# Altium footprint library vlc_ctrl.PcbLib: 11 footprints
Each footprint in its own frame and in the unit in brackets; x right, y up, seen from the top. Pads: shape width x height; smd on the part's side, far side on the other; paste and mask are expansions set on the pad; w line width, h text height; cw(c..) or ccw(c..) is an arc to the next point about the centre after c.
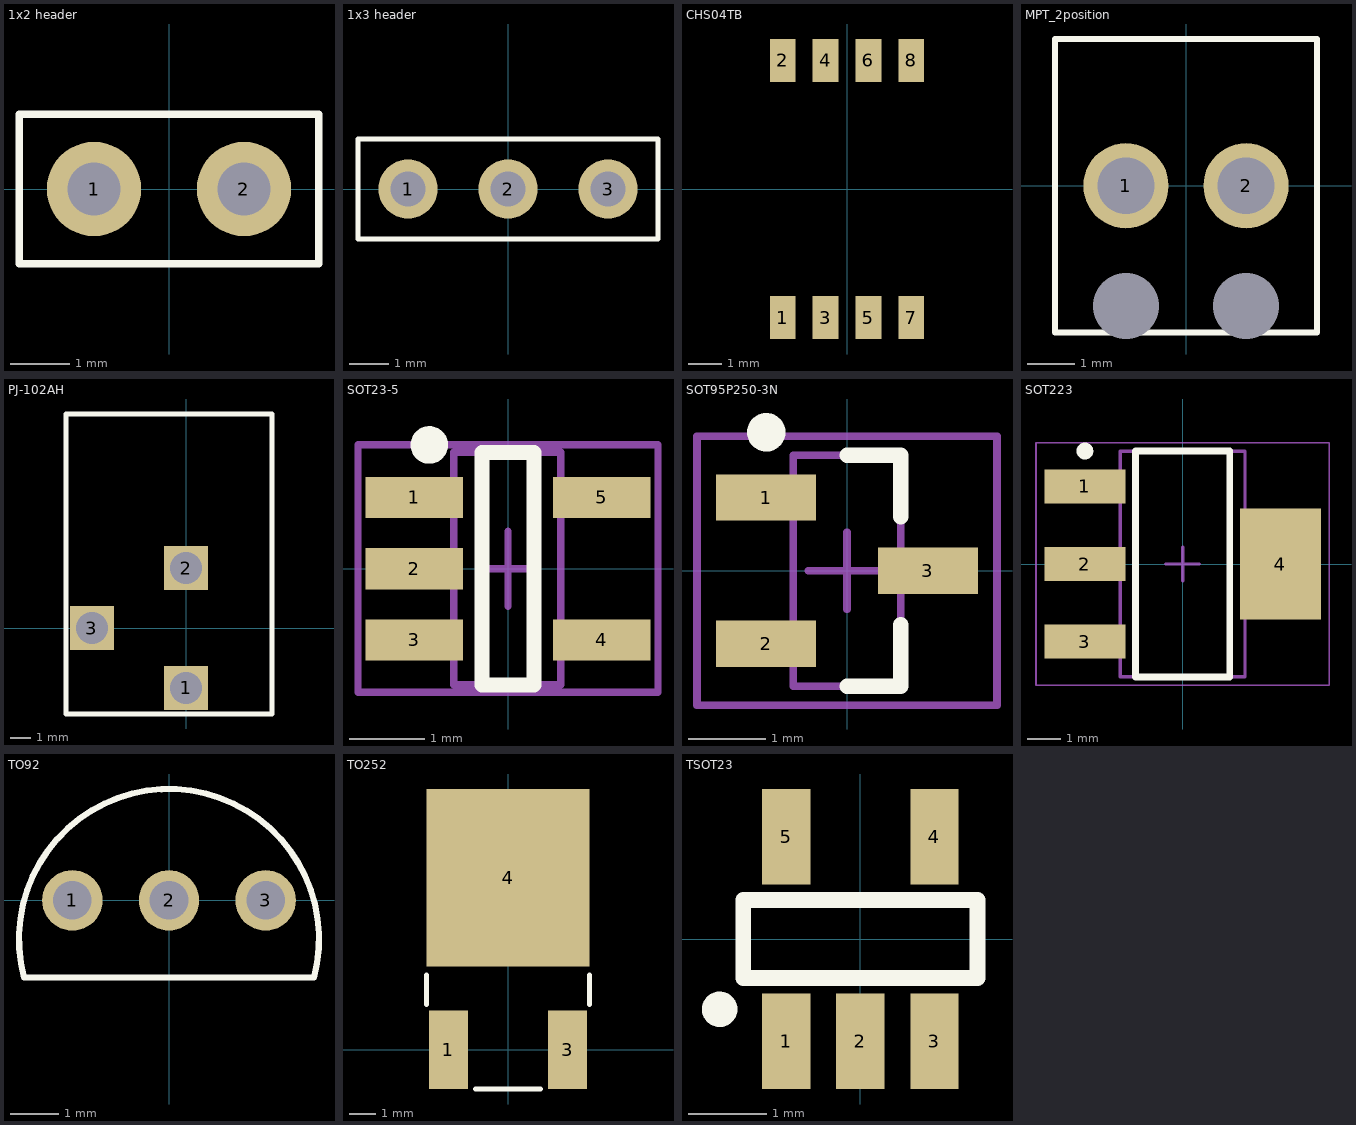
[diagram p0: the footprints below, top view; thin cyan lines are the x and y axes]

## 1x2 header [mm] "1x2 header, 100 mils"
pads (2):
  round 1.6 hole 0.9: 1(-1.27,0) 2(1.27,0)
Top Overlay:
  lines w0.127: -2.54,-1.27 -2.54,1.27 2.54,1.27 2.54,-1.27 -2.54,-1.27
3D body: height 2.54, standoff 0, extent -2.53,-1.26 2.53,1.26
3D body: height 8.38, standoff -1.52, extent -1.575,-0.305 -0.965,0.305
3D body: height 8.38, standoff -1.52, extent 0.965,-0.305 1.575,0.305

## 1x3 header [mm] "1x3 header, 100 mils"
pads (3):
  round 1.5 hole 0.9: 1(-2.54,0) 2(0,0) 3(2.54,0)
Top Overlay:
  lines w0.127: -3.81,-1.27 3.81,-1.27 3.81,1.27 -3.81,1.27 -3.81,-1.27
3D body: height 8.38, standoff -1.52, extent 2.235,-0.305 2.845,0.305
3D body: height 8.38, standoff -1.52, extent -0.305,-0.305 0.305,0.305
3D body: height 8.38, standoff -1.52, extent -2.845,-0.305 -2.235,0.305
3D body: height 2.54, standoff 0, extent -3.8,-1.25 3.8,1.25

## CHS04TB [mm] "4 POS DIP SWITCH"
pads (8):
  rect 0.76x1.27 smd: 1(-1.905,-3.81) 2(-1.905,3.81) 3(-0.635,-3.81) 4(-0.635,3.81) 5(0.635,-3.81) 6(0.635,3.81) 7(1.905,-3.81) 8(1.905,3.81)

## MPT_2position [mm] "Screw connector 2 pos"
pads (4):
  round 1.8 hole 1.2: 1(-1.27,0) 2(1.27,0)
  round 0 hole 1.4: ""(-1.27,-2.54) ""(1.27,-2.54)
Top Overlay:
  lines w0.127: -2.77,-3.1 -2.77,3.1 2.77,3.1 2.77,-3.1 -2.77,-3.1

## PJ-102AH [mm] "Power Jack"
pads (3):
  rect 2.2x2.2 hole 1.6: 1(0,-3) 2(0,3) 3(-4.7,0)
Top Overlay:
  lines w0.254: -6,-4.3 4.3,-4.3 4.3,10.7 -6,10.7 -6,0 -6,-4.3
3D body: height 10, standoff 0, extent -5.75,9.15 4.075,10.888
3D body: height 8.39, standoff 0.01, extent -4.975,-3.85 3.392,9.15
3D body: height 3, standoff 0, extent -5.75,-3.987 4.075,10.888

## SOT23-5 [mm] "SOT23, 5-Leads, Body 2.9x1.6mm, Pitch 0.95mm, Lead Span 2.8mm, IPC High Density"
height 1.45
pads (5):
  rect 1.3x0.55 smd: 1(-1.25,0.95) 2(-1.25,0) 3(-1.25,-0.95) 4(1.25,-0.95) 5(1.25,0.95)
Top Overlay:
  circle w0.25: c-1.05,1.65 r0.125
  lines w0.2: -0.35,-1.55 -0.35,1.55 0.35,1.55 0.35,-1.55 -0.35,-1.55
Mechanical 13:
  lines w0.1: -0.725,-1.55 0.7,-1.55 0.7,1.55 -0.725,1.55 -0.725,-1.55
Mechanical 15:
  lines w0.1: -0.375,0 0.35,0 ; 0,-0.5 0,0.5 ; -2,-1.65 2,-1.65 2,1.65 -2,1.65 -2,-1.65
3D body: height 1.45, standoff 0, extent -0.675,-1.5 0.65,1.5

## SOT95P250-3N [mm] "SOT23, 3-Leads, Body 2.9x1.3mm, Pitch 0.95mm, Lead Span 2.3mm, IPC Medium Density"
height 1.2
pads (3):
  rect 1.3x0.6 smd: 1(-1.05,0.95) 2(-1.05,-0.95) 3(1.05,0)
Top Overlay:
  circle w0.25: c-1.05,1.8 r0.125
  lines w0.2: 0,-1.5 0.7,-1.5 0.7,-0.7 ; 0,1.5 0.7,1.5 0.7,0.7
Mechanical 13:
  lines w0.1: -0.7,-1.5 0.7,-1.5 0.7,1.5 -0.7,1.5 -0.7,-1.5
Mechanical 15:
  lines w0.1: -0.5,0 0.5,0 ; 0,-0.5 0,0.5 ; -1.95,-1.75 1.95,-1.75 1.95,1.75 -1.95,1.75 -1.95,-1.75
3D body: height 1.2, standoff 0, extent -0.7,-1.5 0.7,1.5

## SOT223 [mm] "SOT223, 4-Leads, Body 6.50x7.00mm (avg), Pitch 2.30mm, IPC Medium Density"
height 1.8
pads (4):
  rect 2.4x1 smd: 1(-2.9,2.3) 2(-2.9,0) 3(-2.9,-2.3)
  rect 2.4x3.3 smd: 4(2.9,0)
Top Overlay:
  circle w0.25: c-2.9,3.35 r0.125
  lines w0.2: -1.4,-3.35 1.4,-3.35 1.4,3.35 -1.4,3.35 -1.4,-3.35
Mechanical 13:
  lines w0.1: -1.85,-3.35 1.85,-3.35 1.85,3.35 -1.85,3.35 -1.85,-3.35
Mechanical 15:
  lines w0.05: -4.35,-3.6 4.35,-3.6 4.35,3.6 -4.35,3.6 -4.35,-3.6
  lines w0.1: -0.5,0 0.5,0 ; 0,-0.5 0,0.5
3D body: height 1.8, standoff 0.02, extent -1.85,-3.35 1.85,3.35

## TO92 [mm]
pads (3):
  round 1.25 hole 0.8: 1(-2,0) 2(0,0) 3(2,0)
Top Overlay:
  lines w0.127: 3,-1.6 -3,-1.6 cw(c0,-0.8) 3,-1.599

## TO252 [mm] "TO252-3"
pads (3):
  rect 1.5x3 smd: 1(-2.286,0) 3(2.286,0)
  rect 6.25x6.8 smd: 4(0,6.6)
Top Overlay:
  lines w0.2: -3.125,1.75 -3.125,2.875 ; -1.25,-1.5 1.25,-1.5 ; 3.125,1.75 3.125,2.875
3D body: height 2.3, standoff 0, extent -3.3,2.975 3.3,9.075

## TSOT23 [mm]
pads (5):
  rect 0.62x1.22 smd: 1(-0.95,-1.31) 2(0,-1.31) 3(0.95,-1.31) 4(0.95,1.31) 5(-0.95,1.31)
Top Overlay:
  circle w0.254: c-1.8,-0.9 r0.1
  lines w0.2: -1.5,-0.5 -1.5,0.5 1.5,0.5 1.5,-0.5 -1.5,-0.5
